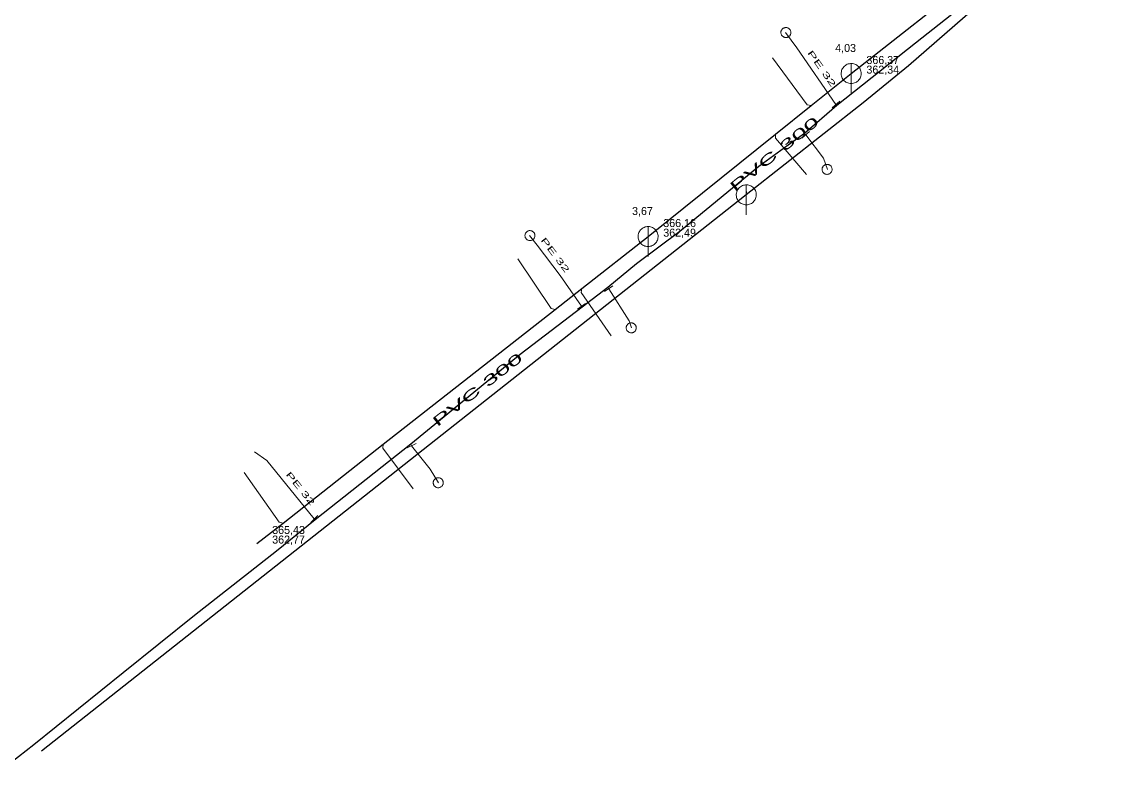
# Model space of a CAD drawing. Extents: x -809916 to -809489, y -991143 to -990912.
# Drawn here: x -809837.8 to -809727.5, y -991063.7 to -990987.3 of the extents above; entities that cross this region are included whole.
import ezdxf

# ---------------------------------------------------------------- set-up
doc = ezdxf.new("R2010")
doc.units = 0
doc.header["$LTSCALE"] = 0.32
doc.layers.add('1', color=7, linetype='Continuous')
for name, color, linetype, lineweight in [('11', 7, 'Continuous', 13), ('13', 7, 'Continuous', 13), ('14', 7, 'Continuous', 25), ('17', 7, 'Continuous', 25), ('19', 7, 'Continuous', 13), ('22', 7, 'Continuous', 13), ('23', 7, 'Continuous', 13), ('34', 7, 'Continuous', 13)]:
    doc.layers.add(name, color=color, linetype=linetype, lineweight=lineweight)

msp = doc.modelspace()

# ---------------------------------------------------------------- linework, layer by layer
at = {"layer": '11'}
msp.add_line((-809765.37, -991004.219), (-809765.379, -991004.55), dxfattribs=at)
for points in [[(-809762.75, -990990.84), (-809759.28, -990995.539), (-809758.89, -990995.62)], [(-809759.37, -991002.53), (-809762.469, -990998.899), (-809762.469, -990998.5)], [(-809788.23, -991010.94), (-809784.877, -991015.901), (-809784.489, -991016)], [(-809778.87, -991018.649), (-809781.87, -991014.32), (-809781.829, -991013.92)], [(-809798.67, -991033.949), (-809801.699, -991029.89), (-809801.67, -991029.489)], [(-809815.57, -991032.3), (-809812.079, -991037.27), (-809811.69, -991037.359)]]:
    msp.add_lwpolyline(points, dxfattribs=at)
at = {"layer": '13'}
for points in [[(-809756.41, -990995.53), (-809760.32, -990989.84), (-809761.449, -990988.32)], [(-809759.44, -990998.55), (-809757.66, -991000.899), (-809757.27, -991002.02)], [(-809781.86, -991015.69), (-809783.989, -991012.62), (-809786.27, -991009.59), (-809787.039, -991008.62)], [(-809779.129, -991013.93), (-809777.1, -991017.14), (-809776.85, -991017.859)], [(-809798.84, -991029.629), (-809796.989, -991031.98), (-809796.149, -991033.34)], [(-809808.57, -991036.949), (-809813.3, -991031.1), (-809814.539, -991030.239)]]:
    msp.add_lwpolyline(points, dxfattribs=at)
at = {"layer": '14', "lineweight": 13}
for p, q in [((-809756.329, -990995.62), (-809756.41, -990995.53)), ((-809759.559, -990998.41), (-809759.44, -990998.55)), ((-809779.219, -991013.8), (-809779.129, -991013.93)), ((-809781.789, -991015.789), (-809781.86, -991015.69)), ((-809798.91, -991029.48), (-809798.84, -991029.629)), ((-809808.489, -991037.03), (-809808.57, -991036.949))]:
    msp.add_line(p, q, dxfattribs=at)
at = {"layer": '14'}
msp.add_line((-809765.379, -991004.55), (-809835.84, -991060.149), dxfattribs=at)
for points in [[(-809754.89, -990992.42), (-809741.98, -990982.27), (-809728.73, -990971.86)], [(-809727.52, -990972.809), (-809749.16, -990991.649), (-809753.69, -990995.359), (-809765.379, -991004.55)], [(-809775.199, -991008.719), (-809762.469, -990998.5), (-809758.89, -990995.62), (-809754.89, -990992.42)], [(-809814.3, -991039.399), (-809811.69, -991037.359), (-809801.67, -991029.489), (-809784.489, -991016), (-809781.829, -991013.92), (-809775.199, -991008.719)]]:
    msp.add_lwpolyline(points, dxfattribs=at)
at = {"layer": '17'}
msp.add_lwpolyline([(-809739.469, -990982.25), (-809748.46, -990989.399), (-809756.329, -990995.62), (-809759.559, -990998.41), (-809761.19, -990999.59), (-809764.129, -991001.73), (-809772.01, -991008.21), (-809776.35, -991011.43), (-809779.219, -991013.8), (-809781.789, -991015.789), (-809787.989, -991020.51), (-809798.91, -991029.48), (-809808.489, -991037.03), (-809812.34, -991040.17), (-809820.55, -991046.6), (-809827.67, -991052.329), (-809836.6, -991059.52), (-809842.02, -991063.739)], dxfattribs=at)
at = {"layer": '22'}
for p, q in [((-809754.89, -990994.42), (-809754.889, -990991.42)), ((-809765.379, -991006.55), (-809765.378, -991003.55)), ((-809775.199, -991010.719), (-809775.198, -991007.719))]:
    msp.add_line(p, q, dxfattribs=at)
for points in [[(-809753.89, -990992.42), (-809753.895, -990992.311), (-809753.913, -990992.203), (-809753.943, -990992.097), (-809753.983, -990991.996), (-809754.035, -990991.899), (-809754.097, -990991.809), (-809754.169, -990991.726), (-809754.249, -990991.652), (-809754.337, -990991.586), (-809754.431, -990991.531), (-809754.531, -990991.486), (-809754.636, -990991.453), (-809754.743, -990991.431), (-809754.852, -990991.421), (-809754.962, -990991.423), (-809755.07, -990991.437), (-809755.177, -990991.462), (-809755.28, -990991.499), (-809755.378, -990991.548), (-809755.47, -990991.606), (-809755.556, -990991.675), (-809755.633, -990991.752), (-809755.702, -990991.838), (-809755.761, -990991.93), (-809755.809, -990992.028), (-809755.846, -990992.131), (-809755.872, -990992.238), (-809755.886, -990992.346), (-809755.889, -990992.456), (-809755.879, -990992.565), (-809755.858, -990992.672), (-809755.824, -990992.776), (-809755.78, -990992.876), (-809755.725, -990992.971), (-809755.659, -990993.059), (-809755.585, -990993.139), (-809755.502, -990993.211), (-809755.412, -990993.273), (-809755.316, -990993.325), (-809755.214, -990993.366), (-809755.109, -990993.396), (-809755.001, -990993.414), (-809754.891, -990993.42), (-809754.782, -990993.414), (-809754.674, -990993.396), (-809754.569, -990993.367), (-809754.467, -990993.326), (-809754.37, -990993.274), (-809754.28, -990993.212), (-809754.197, -990993.141), (-809754.122, -990993.061), (-809754.057, -990992.973), (-809754.001, -990992.879), (-809753.957, -990992.779), (-809753.923, -990992.675), (-809753.901, -990992.567), (-809753.891, -990992.458)], [(-809764.379, -991004.55), (-809764.384, -991004.441), (-809764.402, -991004.333), (-809764.432, -991004.227), (-809764.472, -991004.126), (-809764.524, -991004.029), (-809764.586, -991003.939), (-809764.658, -991003.856), (-809764.738, -991003.782), (-809764.826, -991003.716), (-809764.92, -991003.661), (-809765.02, -991003.616), (-809765.125, -991003.583), (-809765.232, -991003.561), (-809765.341, -991003.551), (-809765.451, -991003.553), (-809765.559, -991003.567), (-809765.666, -991003.592), (-809765.769, -991003.629), (-809765.867, -991003.678), (-809765.959, -991003.736), (-809766.045, -991003.805), (-809766.122, -991003.882), (-809766.191, -991003.968), (-809766.25, -991004.06), (-809766.298, -991004.158), (-809766.335, -991004.261), (-809766.361, -991004.368), (-809766.375, -991004.476), (-809766.378, -991004.586), (-809766.368, -991004.695), (-809766.347, -991004.802), (-809766.313, -991004.906), (-809766.269, -991005.006), (-809766.214, -991005.101), (-809766.148, -991005.189), (-809766.074, -991005.269), (-809765.991, -991005.341), (-809765.901, -991005.403), (-809765.805, -991005.455), (-809765.703, -991005.496), (-809765.598, -991005.526), (-809765.49, -991005.544), (-809765.38, -991005.55), (-809765.271, -991005.544), (-809765.163, -991005.526), (-809765.058, -991005.497), (-809764.956, -991005.456), (-809764.859, -991005.404), (-809764.769, -991005.342), (-809764.686, -991005.271), (-809764.611, -991005.191), (-809764.546, -991005.103), (-809764.49, -991005.009), (-809764.446, -991004.909), (-809764.412, -991004.805), (-809764.39, -991004.697), (-809764.38, -991004.588)], [(-809774.199, -991008.719), (-809774.204, -991008.61), (-809774.222, -991008.502), (-809774.252, -991008.396), (-809774.292, -991008.295), (-809774.344, -991008.198), (-809774.406, -991008.108), (-809774.478, -991008.025), (-809774.558, -991007.951), (-809774.646, -991007.885), (-809774.74, -991007.83), (-809774.84, -991007.785), (-809774.945, -991007.752), (-809775.052, -991007.73), (-809775.161, -991007.72), (-809775.271, -991007.722), (-809775.379, -991007.736), (-809775.486, -991007.761), (-809775.589, -991007.798), (-809775.687, -991007.847), (-809775.779, -991007.905), (-809775.865, -991007.974), (-809775.942, -991008.051), (-809776.011, -991008.137), (-809776.07, -991008.229), (-809776.118, -991008.327), (-809776.155, -991008.43), (-809776.181, -991008.537), (-809776.195, -991008.645), (-809776.198, -991008.755), (-809776.188, -991008.864), (-809776.167, -991008.971), (-809776.133, -991009.075), (-809776.089, -991009.175), (-809776.034, -991009.27), (-809775.968, -991009.358), (-809775.894, -991009.438), (-809775.811, -991009.51), (-809775.721, -991009.572), (-809775.625, -991009.624), (-809775.523, -991009.665), (-809775.418, -991009.695), (-809775.31, -991009.713), (-809775.2, -991009.719), (-809775.091, -991009.713), (-809774.983, -991009.695), (-809774.878, -991009.666), (-809774.776, -991009.625), (-809774.679, -991009.573), (-809774.589, -991009.511), (-809774.506, -991009.44), (-809774.431, -991009.36), (-809774.366, -991009.272), (-809774.31, -991009.178), (-809774.266, -991009.078), (-809774.232, -991008.974), (-809774.21, -991008.866), (-809774.2, -991008.757)]]:
    msp.add_lwpolyline(points, close=True, dxfattribs=at)
at = {"layer": '23'}
for points in [[(-809760.917, -990988.313), (-809760.92, -990988.262), (-809760.93, -990988.21), (-809760.944, -990988.16), (-809760.965, -990988.111), (-809760.99, -990988.066), (-809761.018, -990988.022), (-809761.053, -990987.983), (-809761.09, -990987.946), (-809761.132, -990987.913), (-809761.176, -990987.887), (-809761.224, -990987.863), (-809761.272, -990987.846), (-809761.324, -990987.834), (-809761.375, -990987.826), (-809761.427, -990987.825), (-809761.48, -990987.828), (-809761.532, -990987.838), (-809761.582, -990987.853), (-809761.63, -990987.874), (-809761.676, -990987.898), (-809761.719, -990987.926), (-809761.76, -990987.96), (-809761.796, -990987.999), (-809761.827, -990988.04), (-809761.855, -990988.084), (-809761.877, -990988.131), (-809761.895, -990988.181), (-809761.907, -990988.232), (-809761.914, -990988.283), (-809761.916, -990988.335), (-809761.912, -990988.387), (-809761.903, -990988.439), (-809761.888, -990988.49), (-809761.868, -990988.538), (-809761.844, -990988.583), (-809761.815, -990988.627), (-809761.78, -990988.668), (-809761.743, -990988.703), (-809761.7, -990988.736)], [(-809761.719, -990987.926), (-809761.76, -990987.96), (-809761.796, -990987.999), (-809761.827, -990988.04), (-809761.855, -990988.084), (-809761.877, -990988.131), (-809761.895, -990988.181), (-809761.907, -990988.232), (-809761.914, -990988.283), (-809761.916, -990988.335), (-809761.912, -990988.387), (-809761.903, -990988.439), (-809761.888, -990988.49), (-809761.868, -990988.538), (-809761.844, -990988.583), (-809761.815, -990988.627), (-809761.78, -990988.668), (-809761.743, -990988.703), (-809761.7, -990988.736), (-809761.658, -990988.763), (-809761.61, -990988.786), (-809761.559, -990988.803), (-809761.509, -990988.816), (-809761.456, -990988.823), (-809761.405, -990988.825), (-809761.353, -990988.821), (-809761.301, -990988.81), (-809761.252, -990988.796), (-809761.203, -990988.776), (-809761.157, -990988.751), (-809761.114, -990988.722), (-809761.074, -990988.689), (-809761.037, -990988.651), (-809761.005, -990988.609), (-809760.978, -990988.565), (-809760.956, -990988.518), (-809760.938, -990988.469), (-809760.925, -990988.418), (-809760.918, -990988.365), (-809760.917, -990988.313)], [(-809761.582, -990987.853), (-809761.63, -990987.874), (-809761.676, -990987.898), (-809761.719, -990987.926)], [(-809761.7, -990988.736), (-809761.658, -990988.763), (-809761.61, -990988.786), (-809761.559, -990988.803), (-809761.509, -990988.816), (-809761.456, -990988.823), (-809761.405, -990988.825), (-809761.353, -990988.821), (-809761.301, -990988.81), (-809761.252, -990988.796), (-809761.203, -990988.776), (-809761.157, -990988.751), (-809761.114, -990988.722), (-809761.074, -990988.689), (-809761.037, -990988.651), (-809761.005, -990988.609), (-809760.978, -990988.565), (-809760.956, -990988.518), (-809760.938, -990988.469), (-809760.925, -990988.418), (-809760.918, -990988.365), (-809760.917, -990988.313), (-809760.92, -990988.262), (-809760.93, -990988.21), (-809760.944, -990988.16), (-809760.965, -990988.111), (-809760.99, -990988.066), (-809761.018, -990988.022), (-809761.053, -990987.983), (-809761.09, -990987.946), (-809761.132, -990987.913), (-809761.176, -990987.887), (-809761.224, -990987.863), (-809761.272, -990987.846), (-809761.324, -990987.834), (-809761.375, -990987.826), (-809761.427, -990987.825), (-809761.48, -990987.828), (-809761.532, -990987.838), (-809761.582, -990987.853)], [(-809756.905, -991001.698), (-809756.937, -991001.659), (-809756.975, -991001.623), (-809757.019, -991001.591), (-809757.063, -991001.564), (-809757.111, -991001.542), (-809757.16, -991001.524), (-809757.21, -991001.513), (-809757.263, -991001.507), (-809757.314, -991001.506), (-809757.367, -991001.51), (-809757.418, -991001.521), (-809757.468, -991001.535), (-809757.517, -991001.555), (-809757.563, -991001.58), (-809757.606, -991001.61), (-809757.645, -991001.644), (-809757.68, -991001.683), (-809757.712, -991001.724), (-809757.739, -991001.769), (-809757.762, -991001.817), (-809757.779, -991001.866), (-809757.791, -991001.916), (-809757.797, -991001.969), (-809757.799, -991002.021), (-809757.793, -991002.074), (-809757.783, -991002.124), (-809757.769, -991002.174), (-809757.748, -991002.222), (-809757.723, -991002.269), (-809757.693, -991002.312), (-809757.659, -991002.351), (-809757.621, -991002.387), (-809757.58, -991002.419), (-809757.534, -991002.445), (-809757.488, -991002.468), (-809757.438, -991002.485), (-809757.386, -991002.497), (-809757.334, -991002.504), (-809757.282, -991002.505)], [(-809757.779, -991001.866), (-809757.791, -991001.916), (-809757.797, -991001.969), (-809757.799, -991002.021), (-809757.793, -991002.074), (-809757.783, -991002.124), (-809757.769, -991002.174), (-809757.748, -991002.222), (-809757.723, -991002.269), (-809757.693, -991002.312), (-809757.659, -991002.351), (-809757.621, -991002.387), (-809757.58, -991002.419), (-809757.534, -991002.445), (-809757.488, -991002.468), (-809757.438, -991002.485), (-809757.386, -991002.497), (-809757.334, -991002.504), (-809757.282, -991002.505), (-809757.23, -991002.499), (-809757.179, -991002.49), (-809757.129, -991002.476), (-809757.08, -991002.455), (-809757.034, -991002.43), (-809756.993, -991002.4), (-809756.953, -991002.366), (-809756.917, -991002.328), (-809756.885, -991002.285), (-809756.858, -991002.241), (-809756.837, -991002.194), (-809756.819, -991002.144), (-809756.807, -991002.094), (-809756.8, -991002.041), (-809756.799, -991001.988), (-809756.803, -991001.937), (-809756.813, -991001.886), (-809756.828, -991001.836), (-809756.849, -991001.786), (-809756.873, -991001.742), (-809756.905, -991001.698)], [(-809757.129, -991002.476), (-809757.08, -991002.455), (-809757.034, -991002.43), (-809756.993, -991002.4), (-809756.953, -991002.366), (-809756.917, -991002.328), (-809756.885, -991002.285), (-809756.858, -991002.241), (-809756.837, -991002.194), (-809756.819, -991002.144), (-809756.807, -991002.094), (-809756.8, -991002.041), (-809756.799, -991001.988), (-809756.803, -991001.937), (-809756.813, -991001.886), (-809756.828, -991001.836), (-809756.849, -991001.786), (-809756.873, -991001.742), (-809756.905, -991001.698), (-809756.937, -991001.659), (-809756.975, -991001.623), (-809757.019, -991001.591), (-809757.063, -991001.564), (-809757.111, -991001.542), (-809757.16, -991001.524), (-809757.21, -991001.513), (-809757.263, -991001.507), (-809757.314, -991001.506), (-809757.367, -991001.51), (-809757.418, -991001.521), (-809757.468, -991001.535), (-809757.517, -991001.555), (-809757.563, -991001.58), (-809757.606, -991001.61), (-809757.645, -991001.644), (-809757.68, -991001.683), (-809757.712, -991001.724), (-809757.739, -991001.769), (-809757.762, -991001.817), (-809757.779, -991001.866)], [(-809757.282, -991002.505), (-809757.23, -991002.499), (-809757.179, -991002.49), (-809757.129, -991002.476)], [(-809786.507, -991008.596), (-809786.512, -991008.545), (-809786.524, -991008.493), (-809786.539, -991008.444), (-809786.562, -991008.396), (-809786.588, -991008.351), (-809786.618, -991008.309), (-809786.654, -991008.271), (-809786.692, -991008.235), (-809786.735, -991008.204), (-809786.78, -991008.178), (-809786.828, -991008.156), (-809786.877, -991008.14), (-809786.929, -991008.131), (-809786.98, -991008.124), (-809787.032, -991008.124), (-809787.086, -991008.13), (-809787.137, -991008.141), (-809787.186, -991008.157), (-809787.234, -991008.18), (-809787.279, -991008.205), (-809787.321, -991008.235), (-809787.361, -991008.27), (-809787.396, -991008.31), (-809787.425, -991008.352), (-809787.452, -991008.397), (-809787.473, -991008.445), (-809787.489, -991008.496), (-809787.499, -991008.546), (-809787.505, -991008.598), (-809787.505, -991008.65), (-809787.5, -991008.702), (-809787.489, -991008.754), (-809787.472, -991008.804), (-809787.451, -991008.851), (-809787.425, -991008.896), (-809787.395, -991008.938), (-809787.358, -991008.978), (-809787.321, -991009.012), (-809787.277, -991009.044)], [(-809787.321, -991008.235), (-809787.361, -991008.27), (-809787.396, -991008.31), (-809787.425, -991008.352), (-809787.452, -991008.397), (-809787.473, -991008.445), (-809787.489, -991008.496), (-809787.499, -991008.546), (-809787.505, -991008.598), (-809787.505, -991008.65), (-809787.5, -991008.702), (-809787.489, -991008.754), (-809787.472, -991008.804), (-809787.451, -991008.851), (-809787.425, -991008.896), (-809787.395, -991008.938), (-809787.358, -991008.978), (-809787.321, -991009.012), (-809787.277, -991009.044), (-809787.234, -991009.069), (-809787.186, -991009.091), (-809787.134, -991009.106), (-809787.083, -991009.117), (-809787.03, -991009.123), (-809786.979, -991009.124), (-809786.927, -991009.117), (-809786.875, -991009.106), (-809786.827, -991009.09), (-809786.779, -991009.068), (-809786.734, -991009.041), (-809786.691, -991009.011), (-809786.652, -991008.977), (-809786.617, -991008.937), (-809786.586, -991008.895), (-809786.56, -991008.85), (-809786.54, -991008.802), (-809786.524, -991008.752), (-809786.512, -991008.701), (-809786.507, -991008.648), (-809786.507, -991008.596)], [(-809787.186, -991008.157), (-809787.234, -991008.18), (-809787.279, -991008.205), (-809787.321, -991008.235)], [(-809787.277, -991009.044), (-809787.234, -991009.069), (-809787.186, -991009.091), (-809787.134, -991009.106), (-809787.083, -991009.117), (-809787.03, -991009.123), (-809786.979, -991009.124), (-809786.927, -991009.117), (-809786.875, -991009.106), (-809786.827, -991009.09), (-809786.779, -991009.068), (-809786.734, -991009.041), (-809786.691, -991009.011), (-809786.652, -991008.977), (-809786.617, -991008.937), (-809786.586, -991008.895), (-809786.56, -991008.85), (-809786.54, -991008.802), (-809786.524, -991008.752), (-809786.512, -991008.701), (-809786.507, -991008.648), (-809786.507, -991008.596), (-809786.512, -991008.545), (-809786.524, -991008.493), (-809786.539, -991008.444), (-809786.562, -991008.396), (-809786.588, -991008.351), (-809786.618, -991008.309), (-809786.654, -991008.271), (-809786.692, -991008.235), (-809786.735, -991008.204), (-809786.78, -991008.178), (-809786.828, -991008.156), (-809786.877, -991008.14), (-809786.929, -991008.131), (-809786.98, -991008.124), (-809787.032, -991008.124), (-809787.086, -991008.13), (-809787.137, -991008.141), (-809787.186, -991008.157)], [(-809776.484, -991017.537), (-809776.517, -991017.498), (-809776.555, -991017.462), (-809776.599, -991017.43), (-809776.643, -991017.404), (-809776.691, -991017.381), (-809776.739, -991017.363), (-809776.79, -991017.352), (-809776.843, -991017.346), (-809776.894, -991017.345), (-809776.946, -991017.349), (-809776.998, -991017.36), (-809777.048, -991017.374), (-809777.096, -991017.394), (-809777.142, -991017.419), (-809777.186, -991017.449), (-809777.225, -991017.483), (-809777.259, -991017.521), (-809777.291, -991017.563), (-809777.319, -991017.608), (-809777.342, -991017.656), (-809777.359, -991017.705), (-809777.371, -991017.755), (-809777.377, -991017.808), (-809777.379, -991017.859), (-809777.373, -991017.912), (-809777.363, -991017.963), (-809777.349, -991018.013), (-809777.328, -991018.061), (-809777.304, -991018.107), (-809777.274, -991018.151), (-809777.239, -991018.19), (-809777.201, -991018.226), (-809777.16, -991018.258), (-809777.114, -991018.284), (-809777.068, -991018.307), (-809777.019, -991018.324), (-809776.967, -991018.336), (-809776.915, -991018.343), (-809776.863, -991018.344)], [(-809777.359, -991017.705), (-809777.371, -991017.755), (-809777.377, -991017.808), (-809777.379, -991017.859), (-809777.373, -991017.912), (-809777.363, -991017.963), (-809777.349, -991018.013), (-809777.328, -991018.061), (-809777.304, -991018.107), (-809777.274, -991018.151), (-809777.239, -991018.19), (-809777.201, -991018.226), (-809777.16, -991018.258), (-809777.114, -991018.284), (-809777.068, -991018.307), (-809777.019, -991018.324), (-809776.967, -991018.336), (-809776.915, -991018.343), (-809776.863, -991018.344), (-809776.81, -991018.338), (-809776.76, -991018.329), (-809776.71, -991018.315), (-809776.66, -991018.295), (-809776.614, -991018.269), (-809776.573, -991018.239), (-809776.533, -991018.205), (-809776.497, -991018.167), (-809776.466, -991018.124), (-809776.439, -991018.08), (-809776.417, -991018.033), (-809776.399, -991017.984), (-809776.387, -991017.933), (-809776.38, -991017.881), (-809776.379, -991017.828), (-809776.383, -991017.776), (-809776.393, -991017.726), (-809776.408, -991017.675), (-809776.429, -991017.626), (-809776.453, -991017.581), (-809776.484, -991017.537)], [(-809776.71, -991018.315), (-809776.66, -991018.295), (-809776.614, -991018.269), (-809776.573, -991018.239), (-809776.533, -991018.205), (-809776.497, -991018.167), (-809776.466, -991018.124), (-809776.439, -991018.08), (-809776.417, -991018.033), (-809776.399, -991017.984), (-809776.387, -991017.933), (-809776.38, -991017.881), (-809776.379, -991017.828), (-809776.383, -991017.776), (-809776.393, -991017.726), (-809776.408, -991017.675), (-809776.429, -991017.626), (-809776.453, -991017.581), (-809776.484, -991017.537), (-809776.517, -991017.498), (-809776.555, -991017.462), (-809776.599, -991017.43), (-809776.643, -991017.404), (-809776.691, -991017.381), (-809776.739, -991017.363), (-809776.79, -991017.352), (-809776.843, -991017.346), (-809776.894, -991017.345), (-809776.946, -991017.349), (-809776.998, -991017.36), (-809777.048, -991017.374), (-809777.096, -991017.394), (-809777.142, -991017.419), (-809777.186, -991017.449), (-809777.225, -991017.483), (-809777.259, -991017.521), (-809777.291, -991017.563), (-809777.319, -991017.608), (-809777.342, -991017.656), (-809777.359, -991017.705)], [(-809776.863, -991018.344), (-809776.81, -991018.338), (-809776.76, -991018.329), (-809776.71, -991018.315)], [(-809795.862, -991032.946), (-809795.902, -991032.916), (-809795.947, -991032.888), (-809795.997, -991032.867), (-809796.046, -991032.85), (-809796.097, -991032.839), (-809796.149, -991032.832), (-809796.2, -991032.832), (-809796.253, -991032.838), (-809796.304, -991032.848), (-809796.354, -991032.863), (-809796.402, -991032.885), (-809796.448, -991032.91), (-809796.49, -991032.939), (-809796.53, -991032.974), (-809796.566, -991033.013), (-809796.597, -991033.054), (-809796.622, -991033.099), (-809796.644, -991033.147), (-809796.662, -991033.197), (-809796.673, -991033.249), (-809796.679, -991033.3), (-809796.68, -991033.352), (-809796.674, -991033.404), (-809796.665, -991033.455), (-809796.648, -991033.506), (-809796.627, -991033.553), (-809796.603, -991033.599), (-809796.572, -991033.641), (-809796.538, -991033.681), (-809796.499, -991033.717), (-809796.457, -991033.747), (-809796.412, -991033.775), (-809796.365, -991033.797), (-809796.314, -991033.812), (-809796.264, -991033.825), (-809796.213, -991033.83), (-809796.159, -991033.831), (-809796.107, -991033.826), (-809796.056, -991033.816)], [(-809796.679, -991033.3), (-809796.68, -991033.352), (-809796.674, -991033.404), (-809796.665, -991033.455), (-809796.648, -991033.506), (-809796.627, -991033.553), (-809796.603, -991033.599), (-809796.572, -991033.641), (-809796.538, -991033.681), (-809796.499, -991033.717), (-809796.457, -991033.747), (-809796.412, -991033.775), (-809796.365, -991033.797), (-809796.314, -991033.812), (-809796.264, -991033.825), (-809796.213, -991033.83), (-809796.159, -991033.831), (-809796.107, -991033.826), (-809796.056, -991033.816), (-809796.006, -991033.799), (-809795.959, -991033.779), (-809795.913, -991033.755), (-809795.869, -991033.724), (-809795.83, -991033.689), (-809795.796, -991033.651), (-809795.764, -991033.609), (-809795.738, -991033.564), (-809795.716, -991033.515), (-809795.699, -991033.466), (-809795.688, -991033.416), (-809795.682, -991033.364), (-809795.681, -991033.312), (-809795.685, -991033.259), (-809795.696, -991033.207), (-809795.711, -991033.158), (-809795.732, -991033.111), (-809795.757, -991033.065), (-809795.789, -991033.021), (-809795.822, -991032.983), (-809795.862, -991032.946)], [(-809795.913, -991033.755), (-809795.869, -991033.724), (-809795.83, -991033.689), (-809795.796, -991033.651), (-809795.764, -991033.609), (-809795.738, -991033.564), (-809795.716, -991033.515), (-809795.699, -991033.466), (-809795.688, -991033.416), (-809795.682, -991033.364), (-809795.681, -991033.312), (-809795.685, -991033.259), (-809795.696, -991033.207), (-809795.711, -991033.158), (-809795.732, -991033.111), (-809795.757, -991033.065), (-809795.789, -991033.021), (-809795.822, -991032.983), (-809795.862, -991032.946), (-809795.902, -991032.916), (-809795.947, -991032.888), (-809795.997, -991032.867), (-809796.046, -991032.85), (-809796.097, -991032.839), (-809796.149, -991032.832), (-809796.2, -991032.832), (-809796.253, -991032.838), (-809796.304, -991032.848), (-809796.354, -991032.863), (-809796.402, -991032.885), (-809796.448, -991032.91), (-809796.49, -991032.939), (-809796.53, -991032.974), (-809796.566, -991033.013), (-809796.597, -991033.054), (-809796.622, -991033.099), (-809796.644, -991033.147), (-809796.662, -991033.197), (-809796.673, -991033.249), (-809796.679, -991033.3)], [(-809796.056, -991033.816), (-809796.006, -991033.799), (-809795.959, -991033.779), (-809795.913, -991033.755)]]:
    msp.add_lwpolyline(points, dxfattribs=at)
at = {"layer": '34'}
for p, q in [((-809756.783, -990995.862), (-809756.035, -990995.198)), ((-809759.06, -990998.224), (-809759.819, -990998.875)), ((-809778.718, -991013.644), (-809779.54, -991014.214)), ((-809782.269, -991015.977), (-809781.45, -991015.403)), ((-809798.387, -991029.417), (-809799.293, -991029.839)), ((-809808.923, -991037.302), (-809808.216, -991036.595))]:
    msp.add_line(p, q, dxfattribs=at)

# ---------------------------------------------------------------- texts
at = {"layer": '1'}
for s, height, rotation, width, p in [('PE 32 ', 0.6, 305, 1.95, (-809759.3, -990990.353)), ('PVC 300 ', 1, 39, 2.05, (-809766.531, -991004.308)), ('PE 32 ', 0.6, 307, 1.9, (-809785.974, -991009.084)), ('PVC 300 ', 1, 38, 2.05, (-809796.273, -991027.786)), ('PE 32 ', 0.6, 309, 1.85, (-809811.456, -991032.518))]:
    msp.add_text(s, height=height, rotation=rotation, dxfattribs=dict(at, width=width)).set_placement(p)
for s, p in [('4,03', (-809756.49, -990990.267)), ('3,67', (-809776.799, -991006.567))]:
    msp.add_text(s, height=0.8, dxfattribs=at).set_placement(p)
at = {"layer": '19'}
for s, p in [('366,37', (-809753.368, -990991.471)), ('362,34', (-809753.368, -990992.431)), ('366,16', (-809773.678, -991007.771)), ('362,49', (-809773.678, -991008.731)), ('365,43', (-809812.778, -991038.451)), ('362,77', (-809812.778, -991039.411))]:
    msp.add_text(s, height=0.8, dxfattribs=at).set_placement(p)

doc.saveas('drawing.dxf')
